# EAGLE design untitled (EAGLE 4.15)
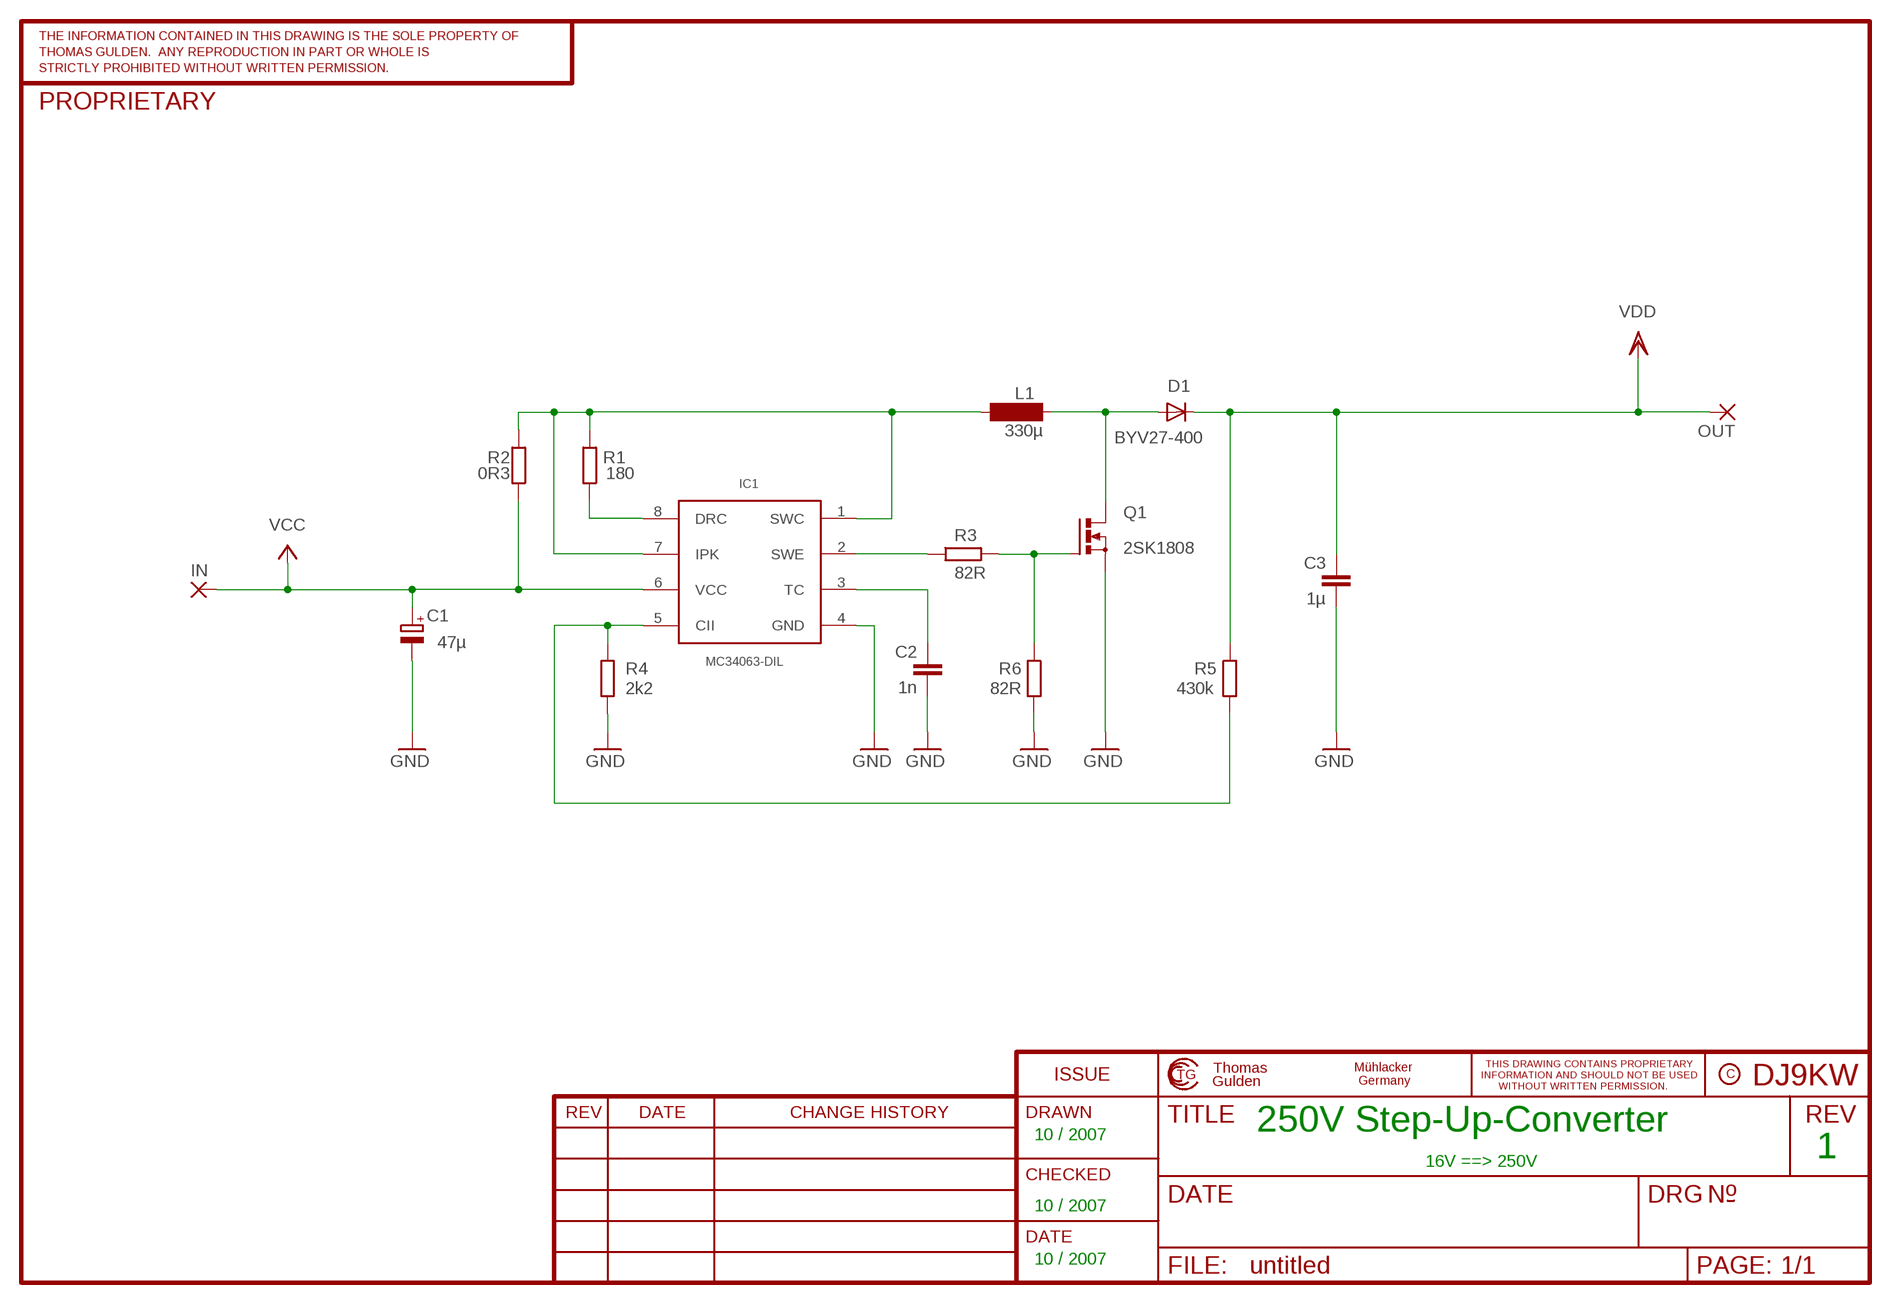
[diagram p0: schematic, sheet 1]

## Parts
C1  47µ  CPOL-EU140CLH-0810  [140CLH-0810]
C2  1n  C-EUC1206K  [C1206K]
C3  1µ  C-EU102-054X133  [C102-054X133]
D1  BYV27-400  BYV27  [SOD57-10]
IC1  MC34063-DIL  [DIL08]
IN  2,54/0,8  [2,54/0,8]
L1  330µ  BS11  [BS11]
OUT  2,54/0,8  [2,54/0,8]
Q1  2SK1808  BUZ11BV  [TO220BV]
R1  180  R-EU_M1206  [M1206]
R2  0R3  R-EU_M1206  [M1206]
R3  82R  R-EU_M1206  [M1206]
R4  2k2  R-EU_M1206  [M1206]
R5  430k  R-EU_M1206  [M1206]
R6  82R  R-EU_M1206  [M1206]

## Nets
GND: C1.- C2.2 C3.2 IC1.4(GND) Q1.S R4.2 R6.2
N$1: IC1.8(DRC) R1.1
N$3: IC1.1(SWC) IC1.7(IPK) L1.2 R1.2 R2.2
N$4: C2.1 IC1.3(TC)
N$5: IC1.2(SWE) R3.1
N$6: Q1.G R3.2 R6.1
N$7: IC1.5(CII) R4.1 R5.2
N$8: D1.A L1.1 Q1.D
VCC: C1.+ IC1.6(VCC) IN.1(P) R2.1
VDD: C3.1 D1.C OUT.1(P) R5.1

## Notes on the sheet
- 250V Step-Up-Converter
- 10 / 2007
- 1
- 16V ==> 250V
- 10 / 2007
- 10 / 2007

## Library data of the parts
C1 = rcl:CPOL-EU: POLARIZED CAPACITOR, European symbol
C2 C3 = rcl:C-EU: CAPACITOR, European symbol
D1 = diode:BYV27: DIODE
IC1 = mc34063:MC34063-DIL: DC/DC converter MC34063 in DIL08.
IN OUT = wirepad:2,54/0,8: THROUGH-HOLE PAD
L1 = inductor-neosid:BS: INDUCTOR
Q1 = transistor-power:BUZ11: N-CHANNEL MOS FET
R1-R6 = rcl:R-EU_: RESISTOR, European symbol

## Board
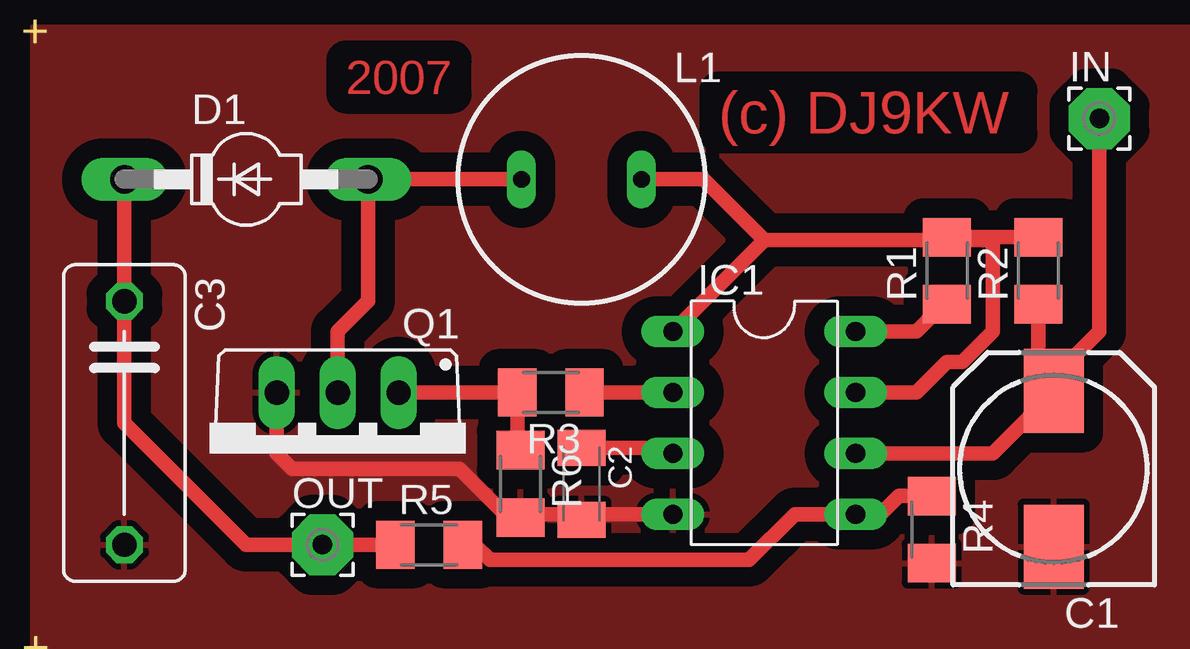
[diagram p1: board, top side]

No outline drawn. Coordinates in mm, seen from the top.
Copper layers (1*16): Top 0.035mm / dielectric 1.5mm / Bottom 0.035mm
Design rules "default": minimum track width 10mil, minimum drill 24mil, track to track 8mil, track to pad 8mil, pad to pad 8mil, via to via 8mil, smd to smd 8mil, copper to edge 40mil, drill to drill 8mil, minimum pad ring 10mil, minimum via ring 8mil, stop-mask expansion 4mil, vias tented up to drill 0mil, thermal gap 10mil

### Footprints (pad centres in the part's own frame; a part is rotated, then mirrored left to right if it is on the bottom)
140CLH-0810 = smd 3.5 x 2.5: + 3.25,0; - -3.25,0
C1206K = smd 1.5 x 2: 1 -1.5,0; 2 1.5,0
C102-054X133 = drill 1.016 octagon: 1 -5.08,0; 2 5.08,0
SOD57-10 = drill 1.194 long: A 5.08,0; C -5.08,0
DIL08 = drill 0.8 long: 1 -3.81,-3.81; 2 -1.27,-3.81; 3 1.27,-3.81; 4 3.81,-3.81; 5 3.81,3.81; 6 1.27,3.81; 7 -1.27,3.81; 8 -3.81,3.81
2,54/0,8 = drill 0.813 pad 2.54 octagon: 1 0,0
BS11 = drill 0.7 long: 1 -2.5,0; 2 2.5,0
TO220BV = drill 1.016 long: D 0,-2.54; G -2.54,-2.54; S 2.54,-2.54
M1206 = smd 1.6 x 2: 1 -1.4,0; 2 1.4,0

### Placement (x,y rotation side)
C1  42.55,7.62 90 top
C2  22.86,6.99 270 top
C3  3.81,9.53 270 top
D1  8.89,19.68 0 top
IC1  30.48,9.53 270 top
IN  44.45,22.23 0 top
L1  22.86,19.68 0 top
OUT  12.06,4.45 0 top
Q1  12.7,8.26 180 top
R1  38.1,15.88 90 top
R2  41.91,15.88 90 top
R3  21.59,10.79 180 top
R4  37.47,5.08 270 top
R5  16.51,4.45 0 top
R6  20.32,6.99 270 top

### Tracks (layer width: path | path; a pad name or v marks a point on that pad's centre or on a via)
GND
  Top 0.61: IC1.4 19.68,5.71 17.78,7.62 10.79,7.62 10.16,8.26 Q1.S
  pour Top (isolate 0.813): 0,26.04 48.9,26.04 48.9,0 0,0
N$1
  Top 0.61: R1.1 38.1,14.61 36.83,13.34 IC1.8
N$3
  Top 0.61: IC1.7 36.83,10.79 38.1,12.06 38.73,12.06 40.01,13.34 40.01,17.14 38.1,17.14 | R2.2 41.91,17.14 41.78,17.27 R1.2 38.1,17.14 | L1.2 27.94,19.68 30.48,17.14 | 30.48,17.14 38.1,17.14 | IC1.1 30.48,17.14
N$4
  Top 0.61: C2.1 26.44,8.48 IC1.3
N$5
  Top 0.61: R3.1 IC1.2
N$6
  Top 0.61: R3.2 20.32,10.79 | Q1.G R3.2 | R6.1 20.32,8.26 20.19,8.38 R3.2
N$7
  Top 0.61: R5.2 18.41,4.45 19.05,3.81 29.84,3.81 31.75,5.71 IC1.5 35.33,5.71 36.09,6.48 37.34,6.48 37.36,6.5 37.39,6.48 R4.1
N$8
  Top 0.61: L1.1 D1.A 13.97,14.61 12.7,13.34 Q1.D
VCC
  Top 0.61: IC1.6 40.01,8.26 41.27,9.53 C1.+ 41.91,10.79 42.55,11.43 | 42.55,11.43 41.91,12.06 R2.1 41.91,11.43 42.55,10.79 42.55,11.43 | 42.55,11.43 44.45,13.34 IN.1
VDD
  Top 0.61: D1.C C3.1 3.81,9.53 8.89,4.45 OUT.1 R5.1 15.24,4.45

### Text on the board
Top: 2007 | (c) DJ9KW
Dimension: + | + | + | +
